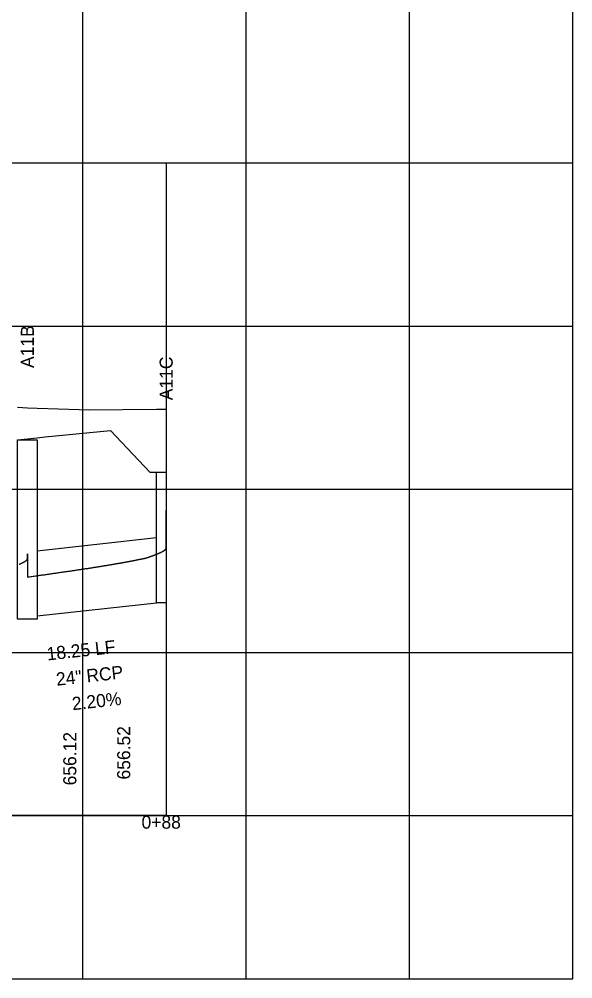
# Model space of a CAD drawing. Extents: x 2252703 to 2264864, y 13787568 to 13790989.
# Drawn here: x 2264678.9 to 2264763.7, y 13789015.9 to 13789162.9 of the extents above; entities that cross this region are included whole.
import ezdxf

# ---------------------------------------------------------------- set-up
doc = ezdxf.new("R2010")
doc.units = 0
for name, color, linetype in [('blank4', 7, 'Continuous'), ('BORD_grid_bottom_major_5int', 7, 'Continuous'), ('D_DRN_PROF_HGL', 7, 'Continuous'), ('D_PROF_1', 7, 'Continuous'), ('D_PROF_NOTES_1', 7, 'Continuous'), ('Default', 7, 'Continuous'), ('Drain_PipeInside', 7, 'Continuous'), ('E_Terrain', 7, 'Continuous'), ('Inlet', 7, 'Continuous'), ('z - Construction', 7, 'Continuous')]:
    doc.layers.add(name, color=color, linetype=linetype)

msp = doc.modelspace()

# ---------------------------------------------------------------- linework, layer by layer
at = {"layer": 'blank4'}
msp.add_lwpolyline([(2264613.67, 13789040.93), (2264613.67, 13789140.93), (2264701.42, 13789140.93), (2264701.42, 13789040.93)], close=True, dxfattribs=at)
at = {"layer": 'BORD_grid_bottom_major_5int'}
for p, q in [((2264688.67, 13789015.93), (2264688.67, 13789315.93)), ((2264713.67, 13789015.93), (2264713.67, 13789315.93)), ((2264738.67, 13789015.93), (2264738.67, 13789315.93)), ((2264763.67, 13789015.93), (2264763.67, 13789315.93)), ((2264413.67, 13789140.93), (2264763.67, 13789140.93)), ((2264413.67, 13789115.93), (2264763.67, 13789115.93)), ((2264413.67, 13789090.93), (2264763.67, 13789090.93)), ((2264413.67, 13789065.93), (2264763.67, 13789065.93)), ((2264413.67, 13789040.93), (2264763.67, 13789040.93)), ((2264413.67, 13789015.93), (2264763.67, 13789015.93))]:
    msp.add_line(p, q, dxfattribs=at)
at = {"layer": 'D_DRN_PROF_HGL'}
msp.add_line((2264680.17, 13789081.04), (2264680.17, 13789077.48), dxfattribs=at)
for points in [[(2264680.17, 13789077.48), (2264680.3, 13789077.5), (2264680.49, 13789077.52), (2264680.68, 13789077.55), (2264680.86, 13789077.58), (2264681.04, 13789077.6), (2264681.22, 13789077.63), (2264681.4, 13789077.65), (2264681.58, 13789077.67), (2264681.75, 13789077.7), (2264681.93, 13789077.72), (2264682.1, 13789077.75), (2264682.27, 13789077.77), (2264682.44, 13789077.79), (2264682.61, 13789077.82), (2264682.78, 13789077.84), (2264682.95, 13789077.86), (2264683.11, 13789077.89), (2264683.27, 13789077.91), (2264683.44, 13789077.93), (2264683.6, 13789077.96), (2264683.76, 13789077.98), (2264683.91, 13789078), (2264684.07, 13789078.02), (2264684.23, 13789078.05), (2264684.38, 13789078.07), (2264684.53, 13789078.09), (2264684.69, 13789078.11), (2264684.84, 13789078.13), (2264684.99, 13789078.15), (2264685.13, 13789078.18), (2264685.28, 13789078.2), (2264685.43, 13789078.22), (2264685.57, 13789078.24), (2264685.71, 13789078.26), (2264685.86, 13789078.28), (2264686, 13789078.3), (2264686.14, 13789078.32), (2264686.28, 13789078.34), (2264686.41, 13789078.36), (2264686.55, 13789078.38), (2264686.69, 13789078.4), (2264686.82, 13789078.42), (2264686.96, 13789078.44), (2264687.09, 13789078.46), (2264687.22, 13789078.48), (2264687.35, 13789078.5), (2264687.48, 13789078.52), (2264687.61, 13789078.54), (2264687.73, 13789078.56), (2264687.86, 13789078.58), (2264687.99, 13789078.59), (2264688.11, 13789078.61), (2264688.23, 13789078.63), (2264688.36, 13789078.65), (2264688.48, 13789078.67), (2264688.6, 13789078.69), (2264688.72, 13789078.7), (2264688.84, 13789078.72), (2264688.95, 13789078.74), (2264689.07, 13789078.76), (2264689.19, 13789078.78), (2264689.3, 13789078.79), (2264689.42, 13789078.81), (2264689.53, 13789078.83), (2264689.64, 13789078.85), (2264689.75, 13789078.86), (2264689.86, 13789078.88), (2264689.97, 13789078.9), (2264690.08, 13789078.91), (2264690.19, 13789078.93), (2264690.3, 13789078.95), (2264690.4, 13789078.97), (2264690.51, 13789078.98), (2264690.61, 13789079), (2264690.72, 13789079.01), (2264690.82, 13789079.03), (2264690.92, 13789079.05), (2264691.03, 13789079.06), (2264691.13, 13789079.08), (2264691.23, 13789079.1), (2264691.33, 13789079.11), (2264691.42, 13789079.13), (2264691.52, 13789079.14), (2264691.62, 13789079.16), (2264691.72, 13789079.17), (2264691.81, 13789079.19), (2264691.91, 13789079.21), (2264692, 13789079.22), (2264692.09, 13789079.24), (2264692.19, 13789079.25), (2264692.28, 13789079.27), (2264692.37, 13789079.28), (2264692.46, 13789079.3), (2264692.55, 13789079.31), (2264692.64, 13789079.33), (2264692.73, 13789079.34), (2264692.81, 13789079.36), (2264692.9, 13789079.37), (2264692.99, 13789079.38), (2264693.07, 13789079.4), (2264693.16, 13789079.41), (2264693.24, 13789079.43), (2264693.33, 13789079.44), (2264693.41, 13789079.46), (2264693.49, 13789079.47), (2264693.57, 13789079.48), (2264693.66, 13789079.5), (2264693.74, 13789079.51), (2264693.82, 13789079.53), (2264693.9, 13789079.54), (2264693.97, 13789079.55), (2264694.05, 13789079.57), (2264694.13, 13789079.58), (2264694.21, 13789079.59), (2264694.28, 13789079.61), (2264694.36, 13789079.62), (2264694.43, 13789079.63), (2264694.51, 13789079.65), (2264694.58, 13789079.66), (2264694.66, 13789079.67), (2264694.73, 13789079.69), (2264694.8, 13789079.7), (2264694.87, 13789079.71), (2264694.94, 13789079.72), (2264695.01, 13789079.74), (2264695.08, 13789079.75), (2264695.15, 13789079.76), (2264695.22, 13789079.78), (2264695.29, 13789079.79), (2264695.36, 13789079.8), (2264695.42, 13789079.81), (2264695.49, 13789079.82), (2264695.56, 13789079.84), (2264695.62, 13789079.85), (2264695.69, 13789079.86), (2264695.75, 13789079.87), (2264695.82, 13789079.89), (2264695.88, 13789079.9), (2264695.94, 13789079.91), (2264696.01, 13789079.92), (2264696.07, 13789079.93), (2264696.13, 13789079.94), (2264696.19, 13789079.96), (2264696.25, 13789079.97), (2264696.31, 13789079.98), (2264696.37, 13789079.99), (2264696.43, 13789080), (2264696.49, 13789080.01), (2264696.55, 13789080.03), (2264696.6, 13789080.04), (2264696.66, 13789080.05), (2264696.72, 13789080.06), (2264696.78, 13789080.07), (2264696.83, 13789080.08), (2264696.89, 13789080.09), (2264696.94, 13789080.1), (2264697, 13789080.12), (2264697.05, 13789080.13), (2264697.1, 13789080.14), (2264697.16, 13789080.15), (2264697.21, 13789080.16), (2264697.26, 13789080.17), (2264697.31, 13789080.18), (2264697.36, 13789080.19), (2264697.42, 13789080.2), (2264697.47, 13789080.21), (2264697.52, 13789080.22), (2264697.57, 13789080.23), (2264697.61, 13789080.24), (2264697.66, 13789080.25), (2264697.71, 13789080.26), (2264697.76, 13789080.27), (2264697.81, 13789080.28), (2264697.85, 13789080.29), (2264697.9, 13789080.3), (2264697.95, 13789080.31), (2264697.99, 13789080.32), (2264698.04, 13789080.34), (2264698.08, 13789080.34), (2264698.13, 13789080.35), (2264698.17, 13789080.36), (2264698.22, 13789080.37), (2264698.26, 13789080.38), (2264698.3, 13789080.39), (2264698.35, 13789080.4), (2264698.39, 13789080.41), (2264698.43, 13789080.42), (2264698.47, 13789080.44), (2264698.51, 13789080.45), (2264698.56, 13789080.47), (2264698.6, 13789080.48), (2264698.64, 13789080.49), (2264698.68, 13789080.51), (2264698.72, 13789080.52), (2264698.75, 13789080.54), (2264698.79, 13789080.55), (2264698.83, 13789080.56), (2264698.87, 13789080.58), (2264698.91, 13789080.59), (2264698.95, 13789080.6), (2264698.98, 13789080.62), (2264699.02, 13789080.63), (2264699.06, 13789080.64), (2264699.09, 13789080.65), (2264699.13, 13789080.67), (2264699.16, 13789080.68), (2264699.2, 13789080.69), (2264699.23, 13789080.71), (2264699.27, 13789080.72), (2264699.3, 13789080.73), (2264699.33, 13789080.74), (2264699.37, 13789080.75), (2264699.4, 13789080.77), (2264699.43, 13789080.78), (2264699.46, 13789080.79), (2264699.5, 13789080.8), (2264699.53, 13789080.82), (2264699.56, 13789080.83), (2264699.59, 13789080.84), (2264699.62, 13789080.85), (2264699.65, 13789080.86), (2264699.68, 13789080.87), (2264699.71, 13789080.89), (2264699.74, 13789080.9), (2264699.77, 13789080.91), (2264699.8, 13789080.92), (2264699.83, 13789080.93), (2264699.85, 13789080.94), (2264699.88, 13789080.95), (2264699.91, 13789080.96), (2264699.94, 13789080.98), (2264699.96, 13789080.99), (2264699.99, 13789081), (2264700.02, 13789081.01), (2264700.04, 13789081.02), (2264700.07, 13789081.03), (2264700.1, 13789081.04), (2264700.12, 13789081.05), (2264700.15, 13789081.06), (2264700.17, 13789081.07), (2264700.19, 13789081.08), (2264700.22, 13789081.09), (2264700.24, 13789081.1), (2264700.27, 13789081.11), (2264700.29, 13789081.12), (2264700.31, 13789081.13), (2264700.34, 13789081.14), (2264700.36, 13789081.15), (2264700.38, 13789081.16), (2264700.4, 13789081.17), (2264700.42, 13789081.18), (2264700.45, 13789081.19), (2264700.47, 13789081.2), (2264700.49, 13789081.21), (2264700.51, 13789081.22), (2264700.53, 13789081.23), (2264700.55, 13789081.24), (2264700.57, 13789081.25), (2264700.59, 13789081.26), (2264700.61, 13789081.27), (2264700.63, 13789081.28), (2264700.64, 13789081.29), (2264700.66, 13789081.3), (2264700.68, 13789081.3), (2264700.7, 13789081.31), (2264700.72, 13789081.32), (2264700.73, 13789081.33), (2264700.75, 13789081.34), (2264700.77, 13789081.35), (2264700.79, 13789081.36), (2264700.8, 13789081.37), (2264700.82, 13789081.37), (2264700.83, 13789081.38), (2264700.85, 13789081.39), (2264700.87, 13789081.4), (2264700.88, 13789081.41), (2264700.9, 13789081.42), (2264700.91, 13789081.42), (2264700.93, 13789081.43), (2264700.94, 13789081.44), (2264700.95, 13789081.45), (2264700.97, 13789081.46), (2264700.98, 13789081.47), (2264701, 13789081.47), (2264701.01, 13789081.48), (2264701.02, 13789081.49), (2264701.03, 13789081.5), (2264701.05, 13789081.5), (2264701.06, 13789081.51), (2264701.07, 13789081.52), (2264701.08, 13789081.53), (2264701.1, 13789081.54), (2264701.11, 13789081.54), (2264701.12, 13789081.55), (2264701.13, 13789081.56), (2264701.14, 13789081.56), (2264701.15, 13789081.57), (2264701.16, 13789081.58), (2264701.17, 13789081.59), (2264701.18, 13789081.59), (2264701.19, 13789081.6), (2264701.2, 13789081.61), (2264701.21, 13789081.62), (2264701.22, 13789081.62), (2264701.23, 13789081.63), (2264701.24, 13789081.64), (2264701.24, 13789081.64), (2264701.25, 13789081.65), (2264701.26, 13789081.66), (2264701.27, 13789081.66), (2264701.28, 13789081.67), (2264701.28, 13789081.68), (2264701.29, 13789081.68), (2264701.3, 13789081.69), (2264701.3, 13789081.7), (2264701.31, 13789081.7), (2264701.32, 13789081.71), (2264701.32, 13789081.72), (2264701.33, 13789081.72), (2264701.33, 13789081.73), (2264701.34, 13789081.73), (2264701.35, 13789081.74), (2264701.35, 13789081.75), (2264701.36, 13789081.75), (2264701.36, 13789081.76), (2264701.37, 13789081.76), (2264701.37, 13789081.77), (2264701.37, 13789081.78), (2264701.38, 13789081.78), (2264701.38, 13789081.79), (2264701.39, 13789081.79), (2264701.39, 13789081.8), (2264701.39, 13789081.81), (2264701.4, 13789081.81), (2264701.4, 13789081.82), (2264701.4, 13789081.82), (2264701.4, 13789081.83), (2264701.41, 13789081.83), (2264701.41, 13789081.84), (2264701.41, 13789081.84), (2264701.41, 13789081.85), (2264701.41, 13789081.86), (2264701.42, 13789081.86), (2264701.42, 13789081.87), (2264701.42, 13789081.87), (2264701.42, 13789081.88), (2264701.42, 13789081.88), (2264701.42, 13789081.89), (2264701.42, 13789081.89), (2264701.42, 13789081.9), (2264701.42, 13789081.9), (2264701.42, 13789087.69)], [(2264678.9, 13789079.43), (2264678.93, 13789079.44), (2264678.95, 13789079.45), (2264678.98, 13789079.46), (2264679, 13789079.47), (2264679.02, 13789079.48), (2264679.05, 13789079.49), (2264679.07, 13789079.5), (2264679.09, 13789079.51), (2264679.12, 13789079.52), (2264679.14, 13789079.53), (2264679.16, 13789079.54), (2264679.18, 13789079.55), (2264679.2, 13789079.56), (2264679.23, 13789079.57), (2264679.25, 13789079.58), (2264679.27, 13789079.59), (2264679.29, 13789079.6), (2264679.31, 13789079.61), (2264679.33, 13789079.62), (2264679.35, 13789079.63), (2264679.37, 13789079.64), (2264679.39, 13789079.65), (2264679.4, 13789079.66), (2264679.42, 13789079.67), (2264679.44, 13789079.67), (2264679.46, 13789079.68), (2264679.48, 13789079.69), (2264679.49, 13789079.7), (2264679.51, 13789079.71), (2264679.53, 13789079.72), (2264679.55, 13789079.73), (2264679.56, 13789079.74), (2264679.58, 13789079.74), (2264679.6, 13789079.75), (2264679.61, 13789079.76), (2264679.63, 13789079.77), (2264679.64, 13789079.78), (2264679.66, 13789079.79), (2264679.67, 13789079.8), (2264679.69, 13789079.8), (2264679.7, 13789079.81), (2264679.72, 13789079.82), (2264679.73, 13789079.83), (2264679.74, 13789079.84), (2264679.76, 13789079.84), (2264679.77, 13789079.85), (2264679.78, 13789079.86), (2264679.8, 13789079.87), (2264679.81, 13789079.88), (2264679.82, 13789079.88), (2264679.83, 13789079.89), (2264679.84, 13789079.9), (2264679.86, 13789079.91), (2264679.87, 13789079.91), (2264679.88, 13789079.92), (2264679.89, 13789079.93), (2264679.9, 13789079.94), (2264679.91, 13789079.94), (2264679.92, 13789079.95), (2264679.93, 13789079.96), (2264679.94, 13789079.96), (2264679.95, 13789079.97), (2264679.96, 13789079.98), (2264679.97, 13789079.99), (2264679.98, 13789079.99), (2264679.99, 13789080), (2264679.99, 13789080.01), (2264680, 13789080.01), (2264680.01, 13789080.02), (2264680.02, 13789080.03), (2264680.03, 13789080.03), (2264680.03, 13789080.04), (2264680.04, 13789080.05), (2264680.05, 13789080.05), (2264680.06, 13789080.06), (2264680.06, 13789080.07), (2264680.07, 13789080.07), (2264680.08, 13789080.08), (2264680.08, 13789080.09), (2264680.09, 13789080.09), (2264680.09, 13789080.1), (2264680.1, 13789080.1), (2264680.1, 13789080.11), (2264680.11, 13789080.12), (2264680.11, 13789080.12), (2264680.12, 13789080.13), (2264680.12, 13789080.13), (2264680.13, 13789080.14), (2264680.13, 13789080.15), (2264680.13, 13789080.15), (2264680.14, 13789080.16), (2264680.14, 13789080.16), (2264680.14, 13789080.17), (2264680.15, 13789080.18), (2264680.15, 13789080.18), (2264680.15, 13789080.19), (2264680.16, 13789080.19), (2264680.16, 13789080.2), (2264680.16, 13789080.2), (2264680.16, 13789080.21), (2264680.16, 13789080.21), (2264680.17, 13789080.22), (2264680.17, 13789080.22), (2264680.17, 13789080.23), (2264680.17, 13789080.23), (2264680.17, 13789080.24), (2264680.17, 13789080.25), (2264680.17, 13789080.25), (2264680.17, 13789080.26), (2264680.17, 13789080.26), (2264680.17, 13789081.04)]]:
    msp.add_lwpolyline(points, dxfattribs=at)
at = {"layer": 'D_PROF_1'}
msp.add_lwpolyline([(2264678.67, 13789098.51), (2264680.17, 13789098.66), (2264680.17, 13789098.66), (2264681.67, 13789098.81), (2264681.67, 13789098.81), (2264682.92, 13789098.94), (2264692.92, 13789099.94), (2264698.92, 13789093.53), (2264699.92, 13789093.53), (2264699.92, 13789093.53), (2264701.42, 13789093.53), (2264701.42, 13789093.53)], dxfattribs=at)
at = {"layer": 'Drain_PipeInside'}
for p, q in [((2264681.67, 13789081.51), (2264699.92, 13789083.52)), ((2264681.67, 13789071.51), (2264699.92, 13789073.52))]:
    msp.add_line(p, q, dxfattribs=at)
at = {"layer": 'E_Terrain'}
msp.add_lwpolyline([(2264678.67, 13789103.48), (2264680.17, 13789103.42), (2264680.17, 13789103.42), (2264681.67, 13789103.36), (2264681.67, 13789103.36), (2264688.08, 13789103.12), (2264689.6, 13789103.11), (2264699.92, 13789103.17), (2264699.92, 13789103.17), (2264701.42, 13789103.18)], dxfattribs=at)
at = {"layer": 'Inlet'}
for points in [[(2264678.67, 13789098.51), (2264681.67, 13789098.51), (2264681.67, 13789071.01), (2264678.67, 13789071.01)], [(2264699.92, 13789093.53), (2264701.42, 13789093.53), (2264701.42, 13789073.52), (2264699.92, 13789073.52)]]:
    msp.add_lwpolyline(points, close=True, dxfattribs=at)
at = {"layer": 'z - Construction'}
for p, q in [((2264613.67, 13789115.93), (2264701.42, 13789115.93)), ((2264613.67, 13789090.93), (2264701.42, 13789090.93)), ((2264613.67, 13789065.93), (2264701.42, 13789065.93))]:
    msp.add_line(p, q, dxfattribs=at)

# ---------------------------------------------------------------- texts
at = {"layer": 'D_PROF_NOTES_1'}
for s, rotation, p in [('A11B', 90, (2264681.17, 13789109.5)), ('A11C', 90, (2264702.42, 13789104.56)), ('18.25 LF', 6.2773, (2264683.24, 13789064.69)), ('24" RCP', 6.2773, (2264684.68, 13789060.82)), ('2.20%', 6.2773, (2264687.11, 13789057.07)), ('656.52', 90, (2264695.92, 13789046.46)), ('656.12', 90, (2264687.67, 13789045.56))]:
    msp.add_text(s, height=2, rotation=rotation, dxfattribs=at).set_placement(p)
at = {"layer": 'Default'}
msp.add_text('0+88', height=2, dxfattribs=at).set_placement((2264697.65, 13789038.93))

doc.saveas('drawing.dxf')
